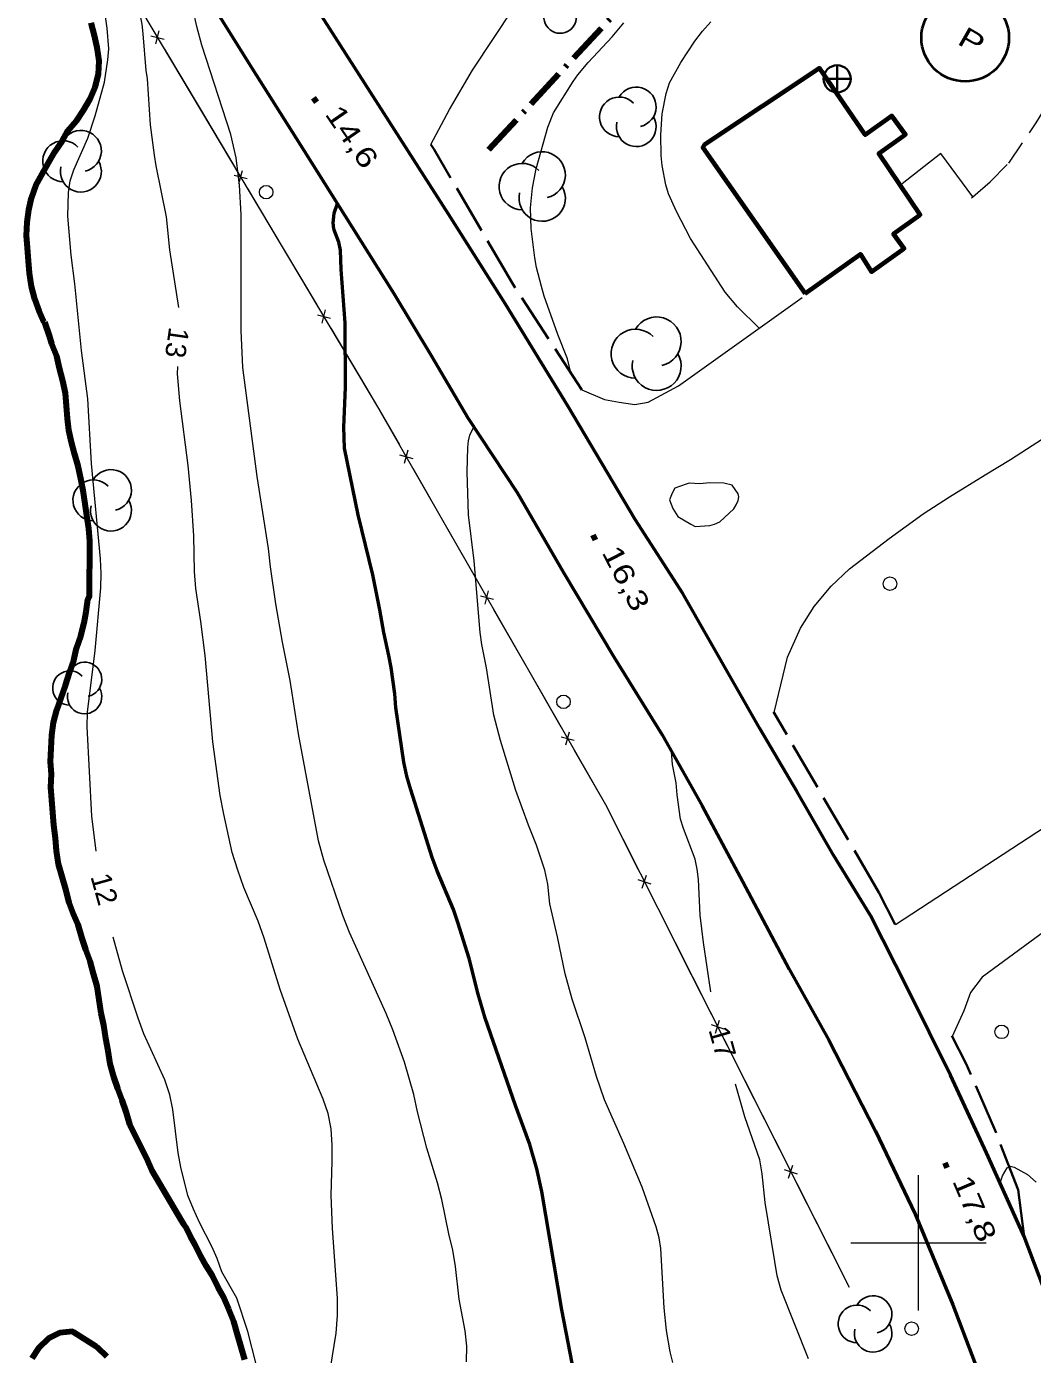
# Model space of a CAD drawing. Extents: x 355726 to 357533, y 5103782 to 5105258.
# Drawn here: x 356234.1 to 356308.4, y 5104991.8 to 5105089.8 of the extents above; entities that cross this region are included whole.
import ezdxf
from ezdxf.enums import TextEntityAlignment as Align

# ---------------------------------------------------------------- set-up
doc = ezdxf.new("R2010")
doc.units = 0
doc.header["$LTSCALE"] = 0.6
for name, pattern in [('DASH_DOUBLE_DOT', [9.2, 5, -1.2, 0.3, -1.2, 0.3, -1.2]), ('DOT_DASHED', [7.7, 5, -1.2, 0.3, -1.2]), ('LONG_DASHED', [7.5, 6, -1.5]), ('MEDIUM_DASHED', [4.5, 3, -1.5])]:
    doc.linetypes.add(name, pattern=pattern)
for name, color, linetype, lineweight in [('1', 7, 'LONG_DASHED', 53), ('19', 7, 'Continuous', 13), ('2', 7, 'LONG_DASHED', 13), ('21', 7, 'LONG_DASHED', 35), ('3', 7, 'Continuous', 140), ('31', 7, 'Continuous', 35), ('34', 7, 'Continuous', 35), ('36', 7, 'Continuous', 13), ('37', 7, 'Continuous', 13), ('38', 7, 'Continuous', 40), ('4', 7, 'DASH_DOUBLE_DOT', 53), ('41', 7, 'DOT_DASHED', 90), ('44', 7, 'Continuous', 25), ('61', 7, 'Continuous', 13)]:
    doc.layers.add(name, color=color, linetype=linetype, lineweight=lineweight)

msp = doc.modelspace()

# ---------------------------------------------------------------- linework, layer by layer
at = {"layer": '1', "linetype": 'Continuous'}
for points in [[(356256.8, 5105074.86), (356256.76, 5105075.33), (356256.82, 5105076.05), (356257.06, 5105076.76)], [(356274.72, 5104989.46), (356273.66, 5104995.05), (356272.18, 5105003.8), (356271.8, 5105005.47), (356271.28, 5105007.25), (356270.22, 5105010.15), (356267.99, 5105016.59), (356267.46, 5105018.36), (356266.81, 5105021), (356265.96, 5105023.67), (356265.63, 5105024.61), (356264.43, 5105027.47), (356264.07, 5105028.46), (356262.5, 5105033.46), (356262.2, 5105034.47), (356261.96, 5105035.51), (356261.39, 5105039.55), (356261.3, 5105040.54), (356261.03, 5105042.49), (356260.87, 5105043.37), (356260.49, 5105045.08), (356260.2, 5105046.75), (356259.67, 5105049.33), (356258.59, 5105053.76), (356257.59, 5105058.69), (356257.54, 5105060.24), (356257.66, 5105063.17), (356257.63, 5105067.94), (356257.33, 5105071.88), (356257.28, 5105073.33), (356257.16, 5105073.92), (356256.8, 5105074.86)]]:
    msp.add_lwpolyline(points, dxfattribs=at)
at = {"layer": '19'}
msp.add_line((356298.3, 5105023.5), (356314.35, 5105034.01), dxfattribs=at)
for points in [[(356263.96, 5105081.13), (356265.34, 5105083.7), (356267.04, 5105086.61), (356270.1, 5105091.22), (356273.81, 5105094.23), (356277.32, 5105097.62), (356281.89, 5105102.3), (356286.45, 5105106.88), (356290.06, 5105110.13), (356293.17, 5105112.94), (356298.33, 5105118.54), (356301.48, 5105121.72), (356304.15, 5105124.8), (356305.04, 5105125.99)], [(356304.01, 5105077.25), (356301.66, 5105080.47), (356298.81, 5105078.22)], [(356275.13, 5105063.01), (356276.79, 5105062.3), (356277.88, 5105062.08), (356279.04, 5105061.92), (356280.02, 5105062.08), (356282.27, 5105063.3), (356291.41, 5105069.83)], [(356289.33, 5105039.16), (356290.33, 5105043.26), (356291.29, 5105045.4), (356292.29, 5105046.99), (356293.56, 5105048.51), (356294.91, 5105049.79), (356297.85, 5105052.01), (356300.34, 5105053.84), (356302.29, 5105055.11), (356304.94, 5105056.73), (356306.8, 5105057.86), (356309.18, 5105059.38), (356311.15, 5105060.95), (356313.29, 5105062.4), (356315.17, 5105063.72), (356316.84, 5105064.8), (356318.24, 5105065.47), (356320.8, 5105066.87)], [(356321.32, 5105038.65), (356325.08, 5105040.93), (356327.8, 5105036.57), (356304.72, 5105019.63), (356303.85, 5105018.5), (356303.35, 5105017.13), (356302.5, 5105015.23)]]:
    msp.add_lwpolyline(points, dxfattribs=at)
at = {"layer": '19', "linetype": 'MEDIUM_DASHED'}
msp.add_lwpolyline([(356303.93, 5105077.18), (356304.01, 5105077.25), (356305.29, 5105078.37), (356306.68, 5105079.75), (356308.7, 5105082.72), (356309.87, 5105084.65), (356311.13, 5105086.84), (356312.04, 5105088.55), (356313.11, 5105090.86), (356313.98, 5105092.79), (356314.63, 5105094.63), (356314.72, 5105095.96), (356314.33, 5105097.74), (356313.36, 5105099.26), (356312.16, 5105101.05), (356311.17, 5105102.45), (356310.39, 5105103.42), (356309.17, 5105104.54)], dxfattribs=at)
at = {"layer": '19'}
msp.add_lwpolyline([(356282, 5105055.74), (356281.79, 5105055.36), (356281.61, 5105054.87), (356281.85, 5105054.24), (356282.21, 5105053.64), (356283.19, 5105053.09), (356283.49, 5105052.92), (356284.58, 5105052.97), (356284.93, 5105053.07), (356285.33, 5105053.25), (356286.35, 5105054.22), (356286.52, 5105054.52), (356286.69, 5105054.83), (356286.74, 5105055.09), (356286.68, 5105055.33), (356286.24, 5105055.97), (356285.63, 5105056.11), (356284.58, 5105056.14), (356283.84, 5105056.06), (356283.46, 5105056.08), (356283.07, 5105056.1), (356282.84, 5105056.03)], close=True, dxfattribs=at)
at = {"layer": '2', "linetype": 'Continuous'}
for points in [[(356245.35, 5105069.09), (356244.69, 5105073.34), (356244.44, 5105075.79), (356243.67, 5105079.55), (356243.55, 5105080.34), (356243.25, 5105082.57), (356243.02, 5105085.97), (356242.93, 5105086.59), (356242.72, 5105089.3), (356242.64, 5105090), (356242.34, 5105091.46), (356241.88, 5105092.94), (356241.06, 5105094.99), (356240.41, 5105096.19), (356239.33, 5105097.97), (356237.66, 5105101.07), (356237.1, 5105102.3), (356236.52, 5105103.84), (356235.94, 5105105.16)], [(356239.23, 5105028.93), (356238.92, 5105031.51), (356238.58, 5105038.12), (356238.6, 5105039.2), (356239.16, 5105043.76), (356239.57, 5105048.38), (356239.6, 5105049.44), (356239.55, 5105050.53), (356238.88, 5105057.55), (356238.61, 5105062.34), (356238.15, 5105065.91), (356237.67, 5105070.84), (356237.38, 5105072.95), (356237.14, 5105075.83), (356237.18, 5105077.58), (356237.31, 5105078.43), (356237.58, 5105079.26), (356238.63, 5105081.59), (356239.15, 5105083.23), (356239.84, 5105085.72), (356240.1, 5105087.38), (356240.16, 5105088.2), (356240.06, 5105089.71), (356239.49, 5105093.71)], [(356266.61, 5104991.21), (356266.62, 5104992.36), (356266.51, 5104993.51), (356266.05, 5104995.84), (356265.79, 5104998.24), (356265.6, 5104999.45), (356265.29, 5105000.66), (356264.77, 5105003.21), (356264.46, 5105004.44), (356263.68, 5105006.99), (356262.98, 5105009.68), (356262.71, 5105010.95), (356262.03, 5105013.34), (356261.17, 5105015.73), (356260.66, 5105016.93), (356257.95, 5105022.92), (356257.46, 5105024.18), (356256.05, 5105028.26), (356255.66, 5105029.69), (356254.2, 5105037.59), (356253.58, 5105041.54), (356253.01, 5105044.37), (356252.51, 5105047.19), (356252.11, 5105049.94), (356251.98, 5105051.29), (356251.13, 5105056.59), (356250.07, 5105064.66), (356249.96, 5105067.38), (356249.96, 5105075.95), (356249.82, 5105078.13), (356249.58, 5105080.13), (356249.19, 5105081.86), (356247.05, 5105088.47), (356246.68, 5105089.83), (356246.41, 5105091.08)], [(356274.31, 5105064.27), (356274.06, 5105065.3), (356273.35, 5105067.09), (356272.35, 5105069.91), (356272.15, 5105070.63), (356271.78, 5105072.05), (356271.65, 5105072.76), (356271.37, 5105074.92), (356271.33, 5105076.44), (356271.49, 5105077.93), (356271.76, 5105079.32), (356272.61, 5105082.41), (356273.04, 5105083.45), (356274.48, 5105085.78), (356274.82, 5105086.26), (356275.59, 5105087.17), (356277.36, 5105089.07), (356278.24, 5105090.11)], [(356288.22, 5105067.55), (356286.64, 5105069.13), (356285.72, 5105070.21), (356283.15, 5105074.18), (356282.12, 5105076.17), (356281.54, 5105077.49), (356281.33, 5105078.15), (356281.07, 5105079.57), (356281, 5105080.3), (356280.96, 5105081.84), (356281.07, 5105083.38), (356281.36, 5105084.9), (356281.61, 5105085.67), (356282.45, 5105087.19), (356283.47, 5105088.75), (356284.04, 5105089.49), (356284.66, 5105090.19)], [(356257.06, 5104994.62), (356257.06, 5104995.92), (356256.7, 5105001.05), (356256.6, 5105003.51), (356256.68, 5105006.01), (356256.68, 5105007.22), (356256.6, 5105008.42), (356256.38, 5105009.55), (356256.01, 5105010.62), (356254.13, 5105015.05), (356252.84, 5105018.72), (356251.66, 5105022.5), (356251.2, 5105023.76), (356250.16, 5105026.24), (356249.7, 5105027.53), (356249.29, 5105028.84), (356248.66, 5105031.65), (356248.41, 5105033.03), (356247.86, 5105037.01), (356247.28, 5105043.38), (356246.97, 5105045.88), (356246.6, 5105048.34), (356246.51, 5105049.59), (356246.45, 5105052.23), (356246.29, 5105054.84), (356246.03, 5105057.42), (356245.41, 5105062.2), (356245.25, 5105064.18), (356245.26, 5105064.73)], [(356281.85, 5104991.17), (356281.66, 5104991.96), (356281.39, 5104993.53), (356281.22, 5104995.2), (356280.96, 5104999.57), (356280.83, 5105000.38), (356280.63, 5105001.17), (356279.59, 5105004.12), (356278.24, 5105007.34), (356276.79, 5105010.55), (356276.2, 5105012.28), (356275.38, 5105015.13), (356274.4, 5105017.99), (356273.9, 5105019.87), (356273.34, 5105022.59), (356272.77, 5105025.04), (356272.61, 5105026.49), (356272.4, 5105027.53), (356271.77, 5105029.38), (356271.18, 5105030.84), (356270.24, 5105033.42), (356269.11, 5105037.09), (356268.63, 5105038.97), (356268.09, 5105042.46), (356267.74, 5105044.2), (356267.61, 5105045.08), (356267.17, 5105050.38), (356266.75, 5105053.76), (356266.66, 5105056.95), (356266.71, 5105058.75), (356266.76, 5105059.24), (356266.86, 5105059.65), (356267.14, 5105060.26)], [(356284.65, 5105018.54), (356284.12, 5105022.17), (356283.87, 5105024.21), (356283.74, 5105026.84), (356283.66, 5105027.61), (356283.5, 5105028.34), (356282.63, 5105030.59), (356282.42, 5105031.28), (356282.16, 5105033.08), (356282.09, 5105033.98), (356281.82, 5105035.32), (356281.75, 5105036.3)], [(356248.51, 5104997.86), (356248.18, 5104998.84), (356247.79, 5104999.73), (356246.87, 5105001.51), (356246.42, 5105002.48), (356246.02, 5105003.49), (356245.49, 5105005.58), (356245.29, 5105006.65), (356244.9, 5105009.84), (356244.69, 5105010.93), (356244.3, 5105012.04), (356242.75, 5105015.44), (356242.33, 5105016.59), (356241.18, 5105020.09), (356240.48, 5105022.57)], [(356291.87, 5104991.42), (356289.85, 5104996.51), (356289.56, 5104997.55), (356289.38, 5104998.63), (356288.67, 5105002.98), (356288.46, 5105005.09), (356288.27, 5105006.12), (356287.17, 5105009.3), (356286.48, 5105011.73)], [(356306.03, 5105004.43), (356306.22, 5105004.96), (356306.55, 5105005.54), (356306.79, 5105005.66), (356307.08, 5105005.58), (356308.07, 5105005.05), (356308.69, 5105004.49)], [(356256.56, 5104990.74), (356256.96, 5104993.32), (356257.06, 5104994.62)]]:
    msp.add_lwpolyline(points, dxfattribs=at)
at = {"layer": '2'}
msp.add_lwpolyline([(356251.07, 5104991.03), (356250.45, 5104993.46), (356249.64, 5104995.9), (356248.51, 5104997.86)], dxfattribs=at)
at = {"layer": '21', "linetype": 'Continuous', "lineweight": 53}
for points in [[(356247.07, 5105092.66), (356250.77, 5105086.74), (356254.6, 5105080.65), (356258.16, 5105075.01), (356261.23, 5105070.12), (356263.98, 5105065.54), (356266.71, 5105060.93), (356270.34, 5105055.43), (356273.76, 5105049.51), (356277.49, 5105043.28), (356281.07, 5105037.51), (356284.01, 5105032.28), (356287.03, 5105026.66), (356290.45, 5105020.21), (356293.38, 5105014.98), (356296.84, 5105008.25), (356299.75, 5105002.12), (356302.55, 5104995.42), (356305.34, 5104988.04), (356307.96, 5104980.11), (356310.35, 5104972.51)], [(356310.45, 5104993.49), (356307.81, 5105000.46), (356305.04, 5105006.65), (356302.36, 5105012.38), (356299.21, 5105018.74), (356296.47, 5105024.17), (356293.73, 5105028.63), (356291.05, 5105033.3), (356288.28, 5105037.98), (356282.59, 5105047.97), (356279.06, 5105053.42), (356274.11, 5105061.78), (356269.48, 5105069.34), (356265.27, 5105075.98), (356254.7, 5105092.51)]]:
    msp.add_lwpolyline(points, dxfattribs=at)
at = {"layer": '21'}
for points in [[(356275.13, 5105063.01), (356269.98, 5105070.9), (356264.21, 5105080.75), (356263.96, 5105081.13)], [(356298.29, 5105023.51), (356297.08, 5105025.88), (356290.12, 5105037.8), (356289.3, 5105039.21)], [(356307.81, 5105000.46), (356307.36, 5105003.91), (356305.68, 5105008.3), (356303.53, 5105013.22), (356302.48, 5105015.28)]]:
    msp.add_lwpolyline(points, dxfattribs=at)
at = {"layer": '3'}
for p, q in [((356255.29, 5105084.57), (356255.52, 5105084.24)), ((356275.93, 5105052.29), (356276.12, 5105051.93)), ((356301.94, 5105005.91), (356302.09, 5105005.54))]:
    msp.add_line(p, q, dxfattribs=at)
at = {"layer": '31', "lineweight": 70}
msp.add_lwpolyline([(356291.62, 5105070.11), (356295.71, 5105073.03), (356296.54, 5105071.72), (356298.95, 5105073.43), (356298.15, 5105074.53), (356300.14, 5105075.92), (356297.07, 5105080.46), (356299.04, 5105081.86), (356298.04, 5105083.23), (356296.06, 5105081.84), (356292.68, 5105086.76), (356284.16, 5105081.09), (356284.06, 5105080.9), (356291.62, 5105070.11)], close=True, dxfattribs=at)
at = {"layer": '34'}
for p, q in [((356293.99, 5105086.97), (356293.99, 5105084.97)), ((356294.99, 5105085.97), (356292.99, 5105085.97))]:
    msp.add_line(p, q, dxfattribs=at)
msp.add_circle((356293.994, 5105085.974), 1, dxfattribs=at)
at = {"layer": '36'}
for centre in [(356251.799, 5105077.6), (356297.899, 5105048.68), (356273.769, 5105039.96), (356306.149, 5105015.58), (356299.499, 5104993.66)]:
    msp.add_circle(centre, 0.5, dxfattribs=at)
at = {"layer": '37'}
for p, q in [((356243.65, 5105088.55), (356243.89, 5105089.52)), ((356243.28, 5105089.15), (356244.25, 5105088.91)), ((356244.28, 5105088.17), (356246.84, 5105083.88)), ((356246.84, 5105083.88), (356249.4, 5105079.58)), ((356249.43, 5105078.85), (356250.4, 5105078.6)), ((356249.79, 5105078.24), (356250.04, 5105079.21)), ((356250.43, 5105077.87), (356252.99, 5105073.57)), ((356252.99, 5105073.57), (356255.55, 5105069.28)), ((356255.94, 5105067.93), (356256.18, 5105068.9)), ((356255.58, 5105068.54), (356256.55, 5105068.29)), ((356256.57, 5105067.56), (356259.14, 5105063.26)), ((356261.66, 5105058.21), (356262.63, 5105057.94)), ((356262.02, 5105057.59), (356262.28, 5105058.56)), ((356262.64, 5105057.21), (356265.13, 5105052.87)), ((356265.13, 5105052.87), (356267.61, 5105048.53)), ((356267.63, 5105047.79), (356268.59, 5105047.53)), ((356267.98, 5105047.18), (356268.24, 5105048.15)), ((356268.61, 5105046.79), (356271.09, 5105042.46)), ((356271.09, 5105042.46), (356273.58, 5105038.12)), ((356273.94, 5105036.77), (356274.21, 5105037.73)), ((356273.59, 5105037.38), (356274.56, 5105037.12)), ((356277.04, 5105032.03), (356279.29, 5105027.57)), ((356279.27, 5105026.83), (356280.22, 5105026.52)), ((356279.59, 5105026.2), (356279.9, 5105027.15)), ((356280.2, 5105025.79), (356282.45, 5105021.32)), ((356282.45, 5105021.32), (356284.71, 5105016.86)), ((356284.68, 5105016.12), (356285.63, 5105015.81)), ((356285, 5105015.49), (356285.31, 5105016.44)), ((356285.61, 5105015.07), (356287.86, 5105010.61)), ((356287.86, 5105010.61), (356290.12, 5105006.15)), ((356290.09, 5105005.41), (356291.04, 5105005.1)), ((356290.41, 5105004.78), (356290.72, 5105005.73)), ((356291.02, 5105004.36), (356293.27, 5104999.9)), ((356293.27, 5104999.9), (356294.88, 5104996.72))]:
    msp.add_line(p, q, dxfattribs=at)
for points in [[(356234.55, 5105104.49), (356260.11, 5105061.63), (356276.87, 5105032.37), (356294.88, 5104996.72)], [(356259.14, 5105063.26), (356260.11, 5105061.63), (356261.65, 5105058.94)], [(356274.57, 5105036.38), (356276.87, 5105032.37), (356277.04, 5105032.03)]]:
    msp.add_lwpolyline(points, dxfattribs=at)
at = {"layer": '38'}
msp.add_circle((356303.455, 5105089.009), 3.235, dxfattribs=at)
at = {"layer": '4', "linetype": 'Continuous', "lineweight": 90}
for points in [[(356235.44, 5105067.99), (356235.37, 5105068.03), (356235.02, 5105068.82), (356234.71, 5105069.69), (356234.45, 5105070.63), (356234.3, 5105071.61), (356234.23, 5105072.54), (356234.16, 5105073.48), (356234.09, 5105074.41), (356234.14, 5105075.38), (356234.26, 5105076.3), (356234.46, 5105077.18), (356234.78, 5105078.1), (356235.24, 5105078.93), (356235.71, 5105079.76), (356236.18, 5105080.59), (356236.72, 5105081.38), (356237.15, 5105082.14), (356237.77, 5105082.88), (356238.31, 5105083.67), (356238.78, 5105084.5), (356239.17, 5105085.37), (356239.41, 5105086.33), (356239.46, 5105087.3), (356239.31, 5105088.28), (356239.12, 5105089.18), (356238.86, 5105090.12)], [(356239.6, 5105016.97), (356239.46, 5105017.95), (356239.31, 5105018.92), (356239.05, 5105019.86), (356238.78, 5105020.81), (356238.48, 5105021.67), (356238.17, 5105022.54), (356237.91, 5105023.48), (356237.56, 5105024.28), (356237.25, 5105025.14), (356236.99, 5105026.09), (356236.72, 5105027.03), (356236.46, 5105027.97), (356236.31, 5105028.95), (356236.24, 5105029.88), (356236.1, 5105030.86), (356236.03, 5105031.79), (356235.96, 5105032.72), (356235.89, 5105033.66), (356235.93, 5105034.62), (356235.86, 5105035.56), (356235.91, 5105036.52), (356235.96, 5105037.49), (356236.08, 5105038.42), (356236.32, 5105039.37), (356236.64, 5105040.29), (356236.96, 5105041.2), (356237.27, 5105042.12), (356237.59, 5105043.03), (356237.79, 5105043.92), (356238.1, 5105044.83), (356238.35, 5105045.79), (356238.5, 5105046.6), (356238.62, 5105047.52), (356238.75, 5105047.75), (356238.76, 5105051.82), (356238.69, 5105052.75), (356238.54, 5105053.73), (356238.43, 5105054.58), (356238.28, 5105055.56), (356238.1, 5105056.46), (356237.91, 5105057.36), (356237.64, 5105058.31), (356237.41, 5105059.13), (356237.22, 5105060.03), (356237.11, 5105060.89), (356237.04, 5105061.82), (356236.97, 5105062.76), (356236.78, 5105063.66), (356236.52, 5105064.6), (356236.33, 5105065.5), (356235.95, 5105066.41), (356235.78, 5105067), (356235.44, 5105067.99)], [(356250.21, 5104991.35), (356249.94, 5104992.29), (356249.68, 5104993.24), (356249.42, 5104994.18), (356249.03, 5104995.09), (356248.65, 5104996), (356248.26, 5104996.71), (356247.84, 5104997.55), (356247.37, 5104998.31), (356246.98, 5104999.02), (356246.56, 5104999.86), (356246.2, 5105000.46), (356245.88, 5105001.13), (356245.74, 5105001.34), (356245.56, 5105001.61), (356243.37, 5105005.32), (356242.99, 5105006.23), (356242.57, 5105007.06), (356242.14, 5105007.9), (356241.72, 5105008.73), (356241.45, 5105009.67), (356241.15, 5105010.54), (356240.84, 5105011.41), (356240.54, 5105012.27), (356240.27, 5105013.22), (356240.13, 5105014.19), (356239.94, 5105015.09), (356239.79, 5105016.07), (356239.6, 5105016.97)], [(356240.02, 5104991.61), (356239.32, 5104992.3), (356239.24, 5104992.34), (356237.55, 5104993.39), (356237.48, 5104993.44), (356236.54, 5104993.36), (356235.71, 5104992.94), (356235.01, 5104992.24), (356234.47, 5104991.45)]]:
    msp.add_lwpolyline(points, dxfattribs=at)
at = {"layer": '41'}
msp.add_line((356268.25, 5105080.75), (356323.61, 5105140.45), dxfattribs=at)
at = {"layer": '44'}
for centre, radius, start, end in [((356273.523, 5105090.545), 1.205, 166.93686, 29.62122), ((356277.892, 5105083.163), 1.465, 44.11537, 269.80396), ((356279.152, 5105083.896), 1.465, 282.26917, 149.72626), ((356279.152, 5105082.431), 1.465, 166.93686, 29.62122), ((356238.103, 5105080.642), 1.515, 282.26917, 149.72626), ((356236.8, 5105079.884), 1.515, 44.11537, 269.80396), ((356272.195, 5105078.875), 1.713, 282.26917, 149.72626), ((356238.103, 5105079.127), 1.515, 166.93686, 29.62122), ((356270.722, 5105078.019), 1.713, 44.11537, 269.80396), ((356272.195, 5105077.162), 1.713, 166.93686, 29.62122), ((356280.656, 5105066.576), 1.809, 282.26917, 149.72626), ((356279.1, 5105065.671), 1.809, 44.11537, 269.80396), ((356280.656, 5105064.766), 1.809, 166.93686, 29.62122), ((356240.332, 5105055.601), 1.513, 282.26917, 149.72626), ((356239.031, 5105054.844), 1.513, 44.11537, 269.80396), ((356240.332, 5105054.088), 1.513, 166.93686, 29.62122), ((356238.381, 5105041.614), 1.27, 282.26917, 149.72626), ((356237.288, 5105040.979), 1.27, 44.11537, 269.80396), ((356238.381, 5105040.344), 1.27, 166.93686, 29.62122), ((356295.456, 5104994.012), 1.388, 44.11537, 269.80396), ((356296.65, 5104994.706), 1.388, 282.26917, 149.72626), ((356296.65, 5104993.317), 1.388, 166.93686, 29.62122)]:
    msp.add_arc(centre, radius, start, end, dxfattribs=at)
at = {"layer": '61'}
for p, q in [((356300, 5104995), (356300, 5105005)), ((356295, 5105000), (356305, 5105000))]:
    msp.add_line(p, q, dxfattribs=at)

# ---------------------------------------------------------------- texts
at = {"layer": '2'}
msp.add_text('13', height=1.5, rotation=261.761, dxfattribs=at).set_placement((356244.475, 5105066.588), align=Align.CENTER)
at = {"layer": '2', "width": 1.05}
for s, rotation, p in [('12', 285.622, (356239.118, 5105025.932)), ('17', 285.822, (356284.793, 5105014.61))]:
    msp.add_text(s, height=1.5, rotation=rotation, dxfattribs=at).set_placement(p, align=Align.CENTER)
at = {"layer": '3', "width": 1.3}
for s, rotation, p in [('14,6   ', 304.484, (356256.09, 5105083.37)), ('16,3   ', 297.294, (356276.57, 5105051)), ('17,8   ', 292.994, (356302.48, 5105004.58))]:
    msp.add_text(s, height=1.5, rotation=rotation, dxfattribs=at).set_placement(p)
at = {"layer": '38', "width": 1.35}
msp.add_text('P', height=1.5, rotation=330.077, dxfattribs=at).set_placement((356302.79, 5105088.59))

doc.saveas('drawing.dxf')
